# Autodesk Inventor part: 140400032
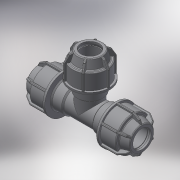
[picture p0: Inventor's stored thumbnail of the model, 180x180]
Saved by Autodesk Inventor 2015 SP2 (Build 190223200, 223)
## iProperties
Created: 2017-08
Part Number: 140400032
Material: Generic
Description: PLASSON L.14 TEE (SILVER) 32-32-32
Document SubType Name: Modeling
Designer: KIM
Density: 1 g/cm^3
Appearance: Default
Author: KIM
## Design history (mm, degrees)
derived "140400.ipt"
feature "Solid1::140400.ipt"
tag "TaggingFeature1"
body "Solid1"
other parameters: "d1" = 32, "d2" = 56, "d4" = 15 deg, "d5" = 36.96, "d6" = 12.1968, "d10" = 61, "d16" = 32.64, "d17" = 2.8, "d22" = 44.8, "d24" = 2.8, "d25" = 54.9, "d26" = 45.75, "d27" = 2.8, "d28" = 135 deg, "d29" = 1.68, "d31" = 1.6, "d46" = 150 deg, "d49" = 3.05, "d50" = 0, "d58" = 0.96, "d61" = 360 deg, "d63" = 28.8, "d64" = 75, "d78" = 180 deg, "d80" = 40.32, "d81" = 2.24, "d84" = 5.6, "d86" = 0, "d88" = 0, "d90" = 0, "d92" = 180 deg, "d_" = 32, "G_" = 18.631, "E_" = 61, "l_" = 56, "l_2" = 19
